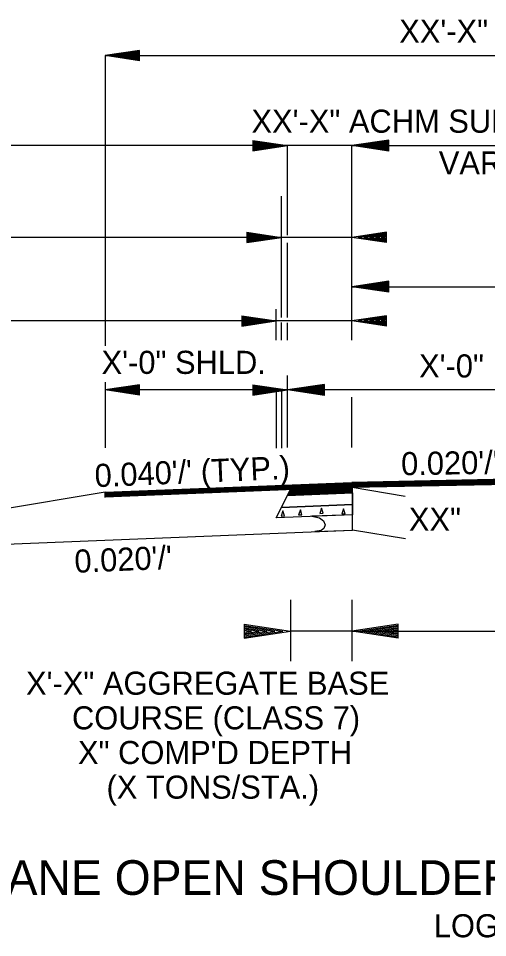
# Model space of a CAD drawing. Extents: x 544199 to 1930787, y -1968972 to 596640.
# Drawn here: x 551692.2 to 551844.7, y -1957268.6 to -1956970.1 of the extents above; entities that cross this region are included whole.
import ezdxf

# ---------------------------------------------------------------- set-up
doc = ezdxf.new("R2010")
doc.units = 0
doc.layers.add('R_Draft', color=7, linetype='Continuous')

msp = doc.modelspace()

# ---------------------------------------------------------------- linework, layer by layer
at = {"layer": 'R_Draft'}
for p, q in [((551731.63, -1956980.49), (551720.38, -1956982.17)), ((551720.38, -1956982.17), (552120.83, -1956982.17)), ((551731.63, -1956983.86), (551720.38, -1956982.17)), ((551720.38, -1956982.17), (551720.38, -1957076.44)), ((551731.63, -1956980.77), (551722.26, -1956982.17)), ((551731.63, -1956983.58), (551722.26, -1956982.17)), ((551731.63, -1956981.05), (551724.19, -1956982.17)), ((551731.63, -1956983.29), (551724.19, -1956982.17)), ((551731.63, -1956981.33), (551726.07, -1956982.17)), ((551731.63, -1956983.01), (551726.07, -1956982.17)), ((551731.63, -1956981.62), (551727.97, -1956982.17)), ((551731.63, -1956982.72), (551727.97, -1956982.17)), ((551731.63, -1956981.91), (551729.85, -1956982.17)), ((551731.63, -1956982.44), (551729.85, -1956982.17)), ((551731.63, -1956983.86), (551731.63, -1956980.49)), ((551768.42, -1957009.72), (551779.67, -1957011.41)), ((551768.42, -1957009.72), (551768.42, -1957013.1)), ((551768.42, -1957010), (551777.79, -1957011.41)), ((551812.64, -1957009.61), (551800.64, -1957011.41)), ((551812.64, -1957009.91), (551802.65, -1957011.41)), ((551812.64, -1957013.21), (551812.64, -1957009.61)), ((551779.67, -1957011.41), (551493.91, -1957011.41)), ((551768.42, -1957010.29), (551775.86, -1957011.41)), ((551768.42, -1957010.57), (551773.98, -1957011.41)), ((551768.42, -1957010.86), (551772.08, -1957011.41)), ((551768.42, -1957011.14), (551770.2, -1957011.41)), ((551768.42, -1957013.1), (551779.67, -1957011.41)), ((551768.42, -1957011.96), (551772.08, -1957011.41)), ((551768.42, -1957012.53), (551775.86, -1957011.41)), ((551768.42, -1957012.81), (551777.79, -1957011.41)), ((551768.42, -1957012.25), (551773.98, -1957011.41)), ((551768.42, -1957011.67), (551770.2, -1957011.41)), ((551800.64, -1957011.41), (551779.67, -1957011.41)), ((551779.67, -1957040.5), (551779.67, -1957011.41)), ((551800.64, -1957011.41), (552040.57, -1957011.41)), ((551812.64, -1957013.21), (551800.64, -1957011.41)), ((551800.64, -1957074.63), (551800.64, -1957011.41)), ((551812.64, -1957012.91), (551802.65, -1957011.41)), ((551812.64, -1957010.21), (551804.71, -1957011.41)), ((551812.64, -1957012.6), (551804.71, -1957011.41)), ((551812.64, -1957010.51), (551806.71, -1957011.41)), ((551812.64, -1957012.3), (551806.71, -1957011.41)), ((551812.64, -1957010.82), (551808.74, -1957011.41)), ((551812.64, -1957011.99), (551808.74, -1957011.41)), ((551812.64, -1957011.13), (551810.75, -1957011.41)), ((551812.64, -1957011.69), (551810.75, -1957011.41)), ((551777.73, -1957041.91), (551777.73, -1957027.88)), ((551766.48, -1957039.54), (551777.73, -1957041.23)), ((551766.48, -1957039.54), (551766.48, -1957042.92)), ((551766.48, -1957039.82), (551775.85, -1957041.23)), ((551811.89, -1957039.54), (551800.64, -1957041.23)), ((551811.89, -1957039.82), (551802.52, -1957041.23)), ((551811.89, -1957042.92), (551811.89, -1957039.54)), ((551777.73, -1957041.23), (551491.98, -1957041.23)), ((551766.48, -1957040.11), (551773.92, -1957041.23)), ((551766.48, -1957040.39), (551772.05, -1957041.23)), ((551766.48, -1957040.68), (551770.14, -1957041.23)), ((551766.48, -1957040.96), (551768.26, -1957041.23)), ((551766.48, -1957042.92), (551777.73, -1957041.23)), ((551766.48, -1957041.78), (551770.14, -1957041.23)), ((551766.48, -1957042.35), (551773.92, -1957041.23)), ((551766.48, -1957042.64), (551775.85, -1957041.23)), ((551766.48, -1957042.07), (551772.05, -1957041.23)), ((551766.48, -1957041.49), (551768.26, -1957041.23)), ((551800.64, -1957041.23), (551777.73, -1957041.23)), ((551777.73, -1957067.26), (551777.73, -1957041.91)), ((551779.67, -1957067.26), (551779.67, -1957042.99)), ((551811.89, -1957042.92), (551800.64, -1957041.23)), ((551811.89, -1957042.64), (551802.52, -1957041.23)), ((551811.89, -1957040.11), (551804.46, -1957041.23)), ((551811.89, -1957042.35), (551804.46, -1957041.23)), ((551811.89, -1957040.39), (551806.33, -1957041.23)), ((551811.89, -1957042.07), (551806.33, -1957041.23)), ((551811.89, -1957040.68), (551808.24, -1957041.23)), ((551811.89, -1957041.77), (551808.24, -1957041.23)), ((551811.89, -1957040.96), (551810.11, -1957041.23)), ((551811.89, -1957041.49), (551810.11, -1957041.23)), ((551812.64, -1957055.43), (551800.64, -1957057.23)), ((551800.64, -1957057.23), (552040.57, -1957057.23)), ((551812.64, -1957059.03), (551800.64, -1957057.23)), ((551812.64, -1957055.73), (551802.65, -1957057.23)), ((551812.64, -1957058.73), (551802.65, -1957057.23)), ((551812.64, -1957056.04), (551804.71, -1957057.23)), ((551812.64, -1957058.43), (551804.71, -1957057.23)), ((551812.64, -1957056.34), (551806.71, -1957057.23)), ((551812.64, -1957058.13), (551806.71, -1957057.23)), ((551812.64, -1957056.64), (551808.74, -1957057.23)), ((551812.64, -1957057.81), (551808.74, -1957057.23)), ((551812.64, -1957056.95), (551810.75, -1957057.23)), ((551812.64, -1957057.51), (551810.75, -1957057.23)), ((551812.64, -1957059.03), (551812.64, -1957055.43)), ((551764.8, -1957066.67), (551776.05, -1957068.36)), ((551764.8, -1957066.67), (551764.8, -1957070.05)), ((551776.05, -1957074.63), (551776.05, -1957064.58)), ((551811.89, -1957066.67), (551800.64, -1957068.36)), ((551811.89, -1957070.05), (551811.89, -1957066.67)), ((551776.05, -1957068.36), (551491.98, -1957068.36)), ((551764.8, -1957066.95), (551774.17, -1957068.36)), ((551764.8, -1957067.24), (551772.23, -1957068.36)), ((551764.8, -1957067.52), (551770.36, -1957068.36)), ((551764.8, -1957067.81), (551768.45, -1957068.36)), ((551764.8, -1957068.09), (551766.57, -1957068.36)), ((551764.8, -1957070.05), (551776.05, -1957068.36)), ((551764.8, -1957068.91), (551768.45, -1957068.36)), ((551764.8, -1957069.48), (551772.23, -1957068.36)), ((551764.8, -1957069.77), (551774.17, -1957068.36)), ((551764.8, -1957069.2), (551770.36, -1957068.36)), ((551764.8, -1957068.62), (551766.57, -1957068.36)), ((551800.64, -1957068.36), (551776.05, -1957068.36)), ((551777.73, -1957074.63), (551777.73, -1957068.89)), ((551779.67, -1957074.63), (551779.67, -1957068.95)), ((551811.89, -1957070.05), (551800.64, -1957068.36)), ((551811.89, -1957066.95), (551802.52, -1957068.36)), ((551811.89, -1957069.77), (551802.52, -1957068.36)), ((551811.89, -1957067.24), (551804.46, -1957068.36)), ((551811.89, -1957069.48), (551804.46, -1957068.36)), ((551811.89, -1957067.52), (551806.33, -1957068.36)), ((551811.89, -1957069.2), (551806.33, -1957068.36)), ((551811.89, -1957067.81), (551808.24, -1957068.36)), ((551811.89, -1957068.9), (551808.24, -1957068.36)), ((551811.89, -1957068.09), (551810.11, -1957068.36)), ((551811.89, -1957068.62), (551810.11, -1957068.36)), ((551779.67, -1957109.43), (551779.67, -1957086.04)), ((551720.38, -1957088.2), (551720.38, -1957109.6)), ((551731.63, -1957089.08), (551720.38, -1957090.77)), ((551731.63, -1957089.36), (551722.26, -1957090.77)), ((551731.63, -1957089.65), (551724.19, -1957090.77)), ((551731.63, -1957089.93), (551726.07, -1957090.77)), ((551731.63, -1957090.22), (551727.97, -1957090.77)), ((551731.63, -1957090.5), (551729.85, -1957090.77)), ((551731.63, -1957092.46), (551731.63, -1957089.08)), ((551768.42, -1957089.08), (551779.67, -1957090.77)), ((551768.42, -1957089.08), (551768.42, -1957092.46)), ((551768.42, -1957089.36), (551777.79, -1957090.77)), ((551768.42, -1957089.65), (551775.86, -1957090.77)), ((551768.42, -1957089.93), (551773.98, -1957090.77)), ((551768.42, -1957090.22), (551772.08, -1957090.77)), ((551768.42, -1957090.5), (551770.2, -1957090.77)), ((551791.67, -1957088.97), (551779.67, -1957090.77)), ((551791.67, -1957089.27), (551781.68, -1957090.77)), ((551791.67, -1957089.58), (551783.74, -1957090.77)), ((551791.67, -1957089.88), (551785.74, -1957090.77)), ((551791.67, -1957090.18), (551787.77, -1957090.77)), ((551791.67, -1957090.49), (551789.78, -1957090.77)), ((551791.67, -1957092.57), (551791.67, -1957088.97)), ((551779.67, -1957090.77), (551720.38, -1957090.77)), ((551731.63, -1957092.46), (551720.38, -1957090.77)), ((551731.63, -1957092.18), (551722.26, -1957090.77)), ((551731.63, -1957091.89), (551724.19, -1957090.77)), ((551731.63, -1957091.61), (551726.07, -1957090.77)), ((551731.63, -1957091.31), (551727.97, -1957090.77)), ((551731.63, -1957091.03), (551729.85, -1957090.77)), ((551768.42, -1957092.46), (551779.67, -1957090.77)), ((551768.42, -1957091.32), (551772.08, -1957090.77)), ((551768.42, -1957091.89), (551775.86, -1957090.77)), ((551768.42, -1957092.18), (551777.79, -1957090.77)), ((551768.42, -1957091.61), (551773.98, -1957090.77)), ((551768.42, -1957091.03), (551770.2, -1957090.77)), ((551776.05, -1957091.48), (551776.05, -1957109.68)), ((551777.73, -1957091.23), (551777.73, -1957109.68)), ((551920.64, -1957090.77), (551779.67, -1957090.77)), ((551791.67, -1957092.57), (551779.67, -1957090.77)), ((551791.67, -1957092.27), (551781.68, -1957090.77)), ((551791.67, -1957091.96), (551783.74, -1957090.77)), ((551791.67, -1957091.66), (551785.74, -1957090.77)), ((551791.67, -1957091.35), (551787.77, -1957090.77)), ((551791.67, -1957091.05), (551789.78, -1957090.77)), ((551800.64, -1957109.43), (551800.64, -1957093.09)), ((551920.64, -1957118.38), (551800.64, -1957120.78)), ((551920.65, -1957118.67), (551800.65, -1957121.07)), ((551920.65, -1957118.97), (551800.65, -1957121.37)), ((551920.66, -1957119.27), (551800.66, -1957121.67)), ((551920.67, -1957119.57), (551800.67, -1957121.97)), ((551920.67, -1957119.87), (551800.67, -1957122.27)), ((551920.68, -1957120.07), (551800.68, -1957122.47)), ((551720.38, -1957123.99), (551800.64, -1957120.78)), ((551720.38, -1957124.29), (551800.65, -1957121.07)), ((551720.38, -1957124.59), (551800.67, -1957121.37)), ((551720.38, -1957124.89), (551800.68, -1957121.67)), ((551720.38, -1957125.19), (551800.69, -1957121.97)), ((551720.38, -1957125.49), (551800.7, -1957122.27)), ((551776.05, -1957132.27), (551780.64, -1957123.08)), ((551780.08, -1957124.2), (551800.75, -1957123.37)), ((551780.23, -1957123.89), (551800.73, -1957123.07)), ((551780.39, -1957123.59), (551800.72, -1957122.77)), ((551780.54, -1957123.28), (551800.71, -1957122.47)), ((551817.97, -1957125.36), (551800.68, -1957122.47)), ((551800.78, -1957136.28), (551800.78, -1957122.47)), ((551720.38, -1957123.99), (551494.58, -1957161.62)), ((551720.38, -1957125.69), (551720.38, -1957123.99)), ((551720.38, -1957125.69), (551720.38, -1957123.99)), ((551779.67, -1957125.02), (551800.78, -1957124.17)), ((551779.77, -1957124.81), (551800.77, -1957123.97)), ((551779.93, -1957124.51), (551800.76, -1957123.67)), ((551597.91, -1957144.4), (551800.78, -1957136.28)), ((551788.56, -1957136.77), (551797.91, -1957136.39)), ((551797.91, -1957136.39), (551800.78, -1957136.28)), ((551818.07, -1957139.16), (551800.78, -1957136.28)), ((551780.64, -1957158.87), (551780.64, -1957178.87)), ((551800.64, -1957158.87), (551800.64, -1957178.87)), ((551765.64, -1957166.87), (551780.64, -1957169.12)), ((551765.64, -1957166.87), (551765.64, -1957171.37)), ((551765.64, -1957167.24), (551778.14, -1957169.12)), ((551765.64, -1957167.62), (551775.56, -1957169.12)), ((551765.64, -1957168), (551773.06, -1957169.12)), ((551815.64, -1957166.87), (551800.64, -1957169.12)), ((551815.64, -1957167.24), (551803.15, -1957169.12)), ((551815.64, -1957167.62), (551805.73, -1957169.12)), ((551815.64, -1957168), (551808.22, -1957169.12)), ((551815.64, -1957171.37), (551815.64, -1957166.87)), ((551765.64, -1957168.39), (551770.52, -1957169.12)), ((551765.64, -1957168.76), (551768.01, -1957169.12)), ((551765.64, -1957171.37), (551780.64, -1957169.12)), ((551765.64, -1957169.85), (551770.52, -1957169.12)), ((551765.64, -1957170.61), (551775.56, -1957169.12)), ((551765.64, -1957170.99), (551778.14, -1957169.12)), ((551765.64, -1957170.23), (551773.06, -1957169.12)), ((551765.64, -1957169.47), (551768.01, -1957169.12)), ((551800.64, -1957169.12), (551780.64, -1957169.12)), ((551800.64, -1957169.12), (552040.57, -1957169.12)), ((551815.64, -1957171.37), (551800.64, -1957169.12)), ((551815.64, -1957170.99), (551803.15, -1957169.12)), ((551815.64, -1957170.61), (551805.73, -1957169.12)), ((551815.64, -1957170.23), (551808.22, -1957169.12)), ((551815.64, -1957168.38), (551810.77, -1957169.12)), ((551815.64, -1957169.84), (551810.77, -1957169.12)), ((551815.64, -1957168.76), (551813.27, -1957169.12)), ((551815.64, -1957169.47), (551813.27, -1957169.12))]:
    msp.add_line(p, q, dxfattribs=at)
for points in [[(551779.67, -1957125.02), (551800.78, -1957124.17), (551800.78, -1957127.98), (551777.73, -1957128.9)], [(551777.73, -1957128.9), (551800.78, -1957127.98), (551800.78, -1957131.28), (551776.05, -1957132.27)]]:
    msp.add_lwpolyline(points, close=True, dxfattribs=at)
for points in [[(551790.78, -1957129.2), (551790.18, -1957130.86), (551791.28, -1957130.81), (551790.78, -1957129.2)], [(551797.91, -1957129.35), (551797.31, -1957131.01), (551798.41, -1957130.97), (551797.91, -1957129.35)], [(551778.19, -1957130.04), (551777.58, -1957131.7), (551778.68, -1957131.65), (551778.19, -1957130.04)], [(551783.86, -1957129.66), (551783.25, -1957131.32), (551784.35, -1957131.27), (551783.86, -1957129.66)], [(551800.78, -1957136.28), (551800.78, -1957131.28), (551787.58, -1957131.8)], [(551787.58, -1957131.8), (551790.04, -1957132.31), (551791.36, -1957133.31), (551791.93, -1957134.57), (551791.47, -1957135.71), (551790.65, -1957136.38), (551788.56, -1957136.77)]]:
    msp.add_lwpolyline(points, dxfattribs=at)

# ---------------------------------------------------------------- texts
for s, height, p in [('XX\'-X" ACHM SURFACE COURSE (1/2")', 7.5, (551815.99, -1956978.01)), ('XX\'-X" ACHM SURFACE COURSE (1/2") FOR LEVELING *', 7.5, (551767.97, -1957007.24)), ('VAR. LBS./SQ. YD. & TACK COAT', 7.5, (551828.86, -1957020.79)), ('X\'-0" SHLD.', 7.5, (551719.26, -1957085.55)), ('X\'-0" LANE', 7.5, (551822.44, -1957086.71)), ('XX"', 7.5, (551819.13, -1957136.51)), ('X\'-X" AGGREGATE BASE', 7.5, (551694.71, -1957189.74)), ('COURSE (CLASS 7)', 7.5, (551709.65, -1957200.99)), ('X" COMP\'D DEPTH', 7.5, (551711.6, -1957212.24)), ('(X TONS/STA.)', 7.5, (551720.87, -1957223.49)), ('2 LANE OPEN SHOULDER OVERLAY WITH MINOR WIDENING', 11.25, (551667.49, -1957254.73)), ('LOG MILE X.XX TO LOG MILE X.XX', 7.5, (551827.23, -1957268.5))]:
    msp.add_text(s, height=height, dxfattribs=at).set_placement(p)
for s, rotation, p in [("0.020'/' (TYP.)", 0.8719, (551816.66, -1957118.47)), ("0.040'/' (TYP.)", 2.448, (551717.17, -1957122.35)), ("0.020'/' ", 2.448, (551710.6, -1957150.17))]:
    msp.add_text(s, height=7.5, rotation=rotation, dxfattribs=at).set_placement(p)

doc.saveas('drawing.dxf')
